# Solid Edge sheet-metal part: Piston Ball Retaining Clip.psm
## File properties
Title: Piston Ball Retaining Clip
Author: Dan
Comments: Spring Steel Strip Width 38.mm x 1.mm Thick  Strip Steel (Orders) 011 763 4261Joleen  Brakpan 011 744 4010  Min order 250.kg  Starco 011-493-6558  ???
Template: Normal.psm
Last saved by: Dan
Revision: 32
Application: Solid Edge
Density: 0 kg/mm^3
Accuracy: 0.99
Material Thickness: 1.1 mm
Bend Radius: 3 mm
Relief Width: 3 mm
Relief Length: 3 mm
Neutral Factor: 0.33
Minimum Arc Length: 0.1 mm
Deviational Tolerance: 0.1 mm
Document Number: P52-014
Project Name: Piston Pump P52
Material: steel
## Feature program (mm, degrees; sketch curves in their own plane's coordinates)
base tab "unnamed BaseTab 1"
dimple "unnamed Dimple 1"
drawn cutout "DrawnCutout_4"
sheet metal cutout "unnamed SheetMetalCutout 1"
pattern "unnamed Pattern 1" of "unnamed SheetMetalCutout 1"
sheet metal cutout "unnamed SheetMetalCutout 2"
sheet metal cutout "unnamed SheetMetalCutout 3"
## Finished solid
Body 1: solid body, 86 faces, 180 edges, 96 vertices.
  Faces by surface: plane 29, spline 24, torus 18, cylinder 9, cone 6
  Edges by curve: line 84, circle 48, intersection 36, curve on surface 12
Bounding box of the edges (mm; curved faces can reach further): 13.510 x 15.343 x 12.000, from (-5.5096, -7.6716, -9.6) to (8, 7.6716, 2.4).
Cylindrical faces by radius (mm): R2.5 x3, R6.9 x3, R8 x3
Conical faces (half-angle, radius in mm at the cone's reference point): 15 deg R3.9375 x3, 15 deg R5 x3
Toroidal faces (ring radius, tube radius in mm): R4.0025 r0.2 x3, R4.0025 r1.3 x3, R6.1035 r0.6 x3, R6.1035 r1.7 x3, R6.5 r0.4 x3, R6.5 r1.5 x3
Planar faces by outward normal: +z 4, -z 7, oblique 18
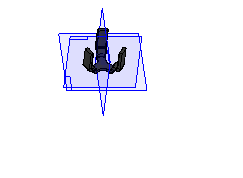
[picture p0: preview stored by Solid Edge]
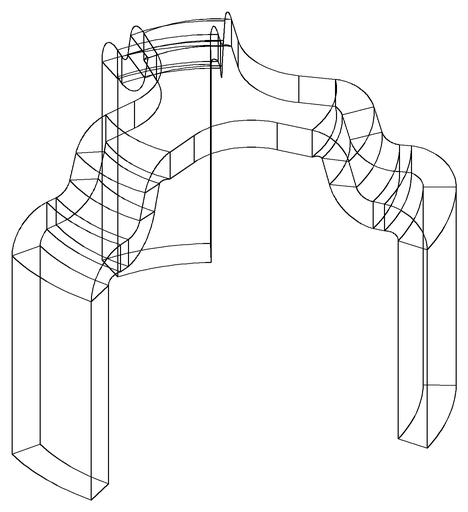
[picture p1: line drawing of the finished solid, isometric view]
